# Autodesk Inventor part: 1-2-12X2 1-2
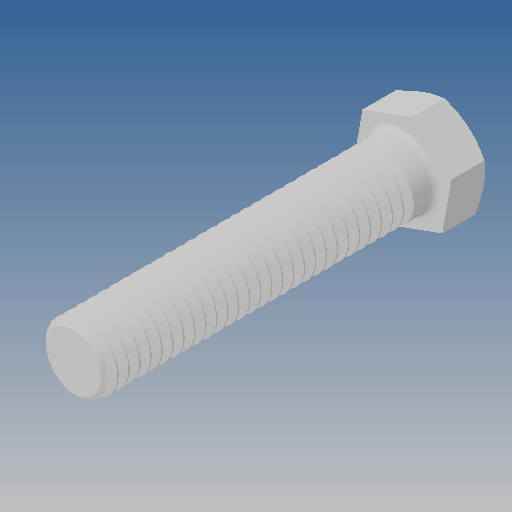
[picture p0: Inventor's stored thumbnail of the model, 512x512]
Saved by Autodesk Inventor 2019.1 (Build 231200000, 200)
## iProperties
Created: 2012-10
Part Number: 1-2-12X2 1-2
Material: Ogólny
Document SubType Name: Modeling
Designer: CADENGINEERING4
Density: 1 g/cm^3
Appearance: Domyślna
Author: CADENGINEERING4
Revision Number: ÈÎºÎ
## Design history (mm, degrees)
feature "ÇÐ³ý-É¨Ãè5"
node "Bryła1"
